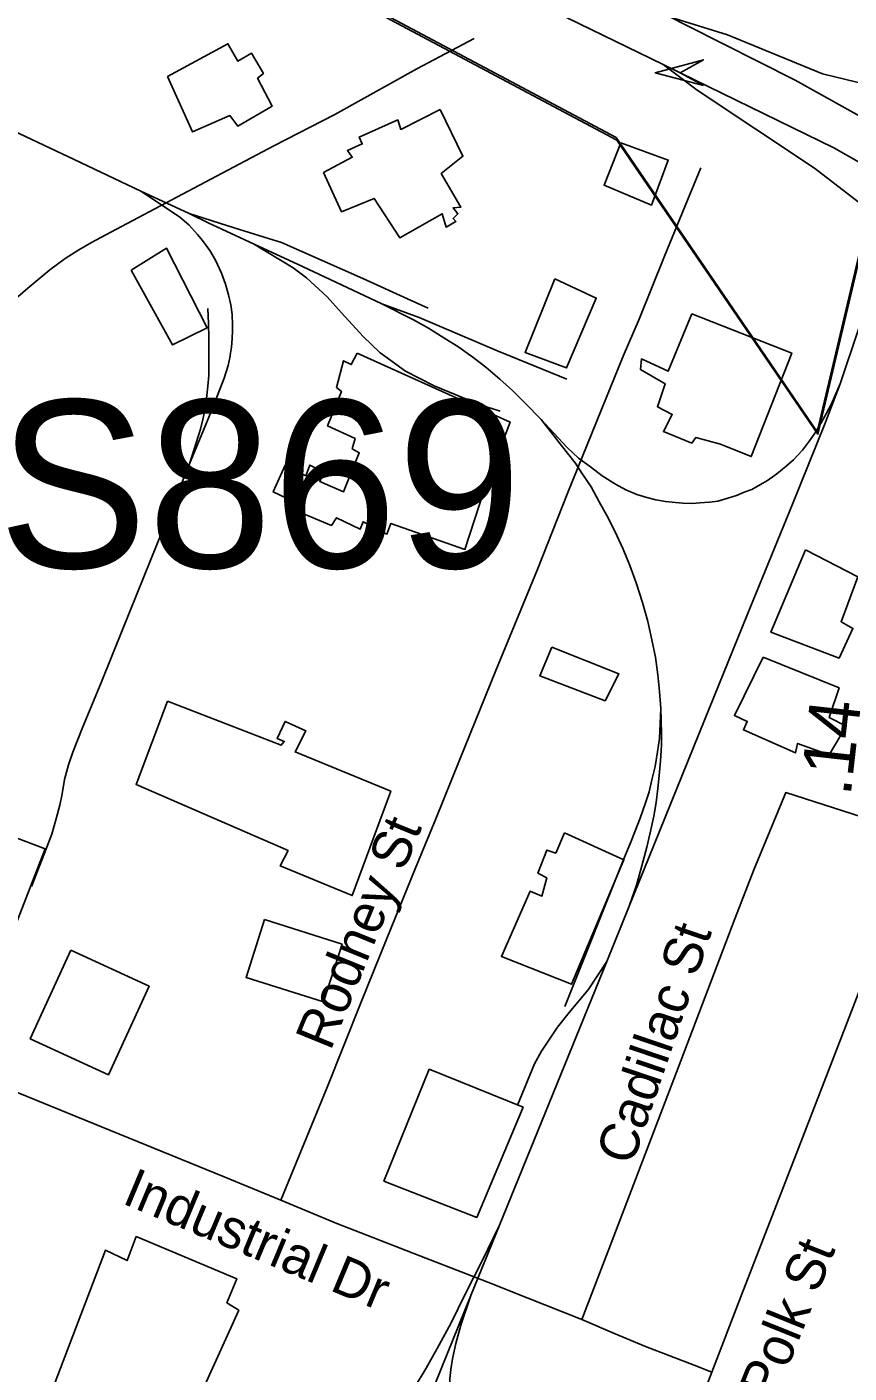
# Model space of a CAD drawing. Extents: x 1383679 to 1536984, y 460658 to 651027.
# Drawn here: x 1434816 to 1436826, y 494579 to 497871 of the extents above; entities that cross this region are included whole.
import ezdxf

# ---------------------------------------------------------------- set-up
doc = ezdxf.new("R2010")
doc.units = 0
for name, color, linetype in [('Default', 7, 'Continuous'), ('Exist Boundary Political City Limit New', 7, 'Continuous'), ('Exist Cultural Warehouse Building Footprint', 7, 'Continuous'), ('Exist Railroad Mainline', 7, 'Continuous'), ('Exist Railroad Spur', 7, 'Continuous'), ('Exist Road Non-System Type 51', 7, 'Continuous'), ('Exist Road Non-System Type 51 Label', 7, 'Continuous'), ('Exist Road Primary Interstate Divided Center Attributed', 7, 'Continuous'), ('Exist Road Primary Interstate Ramp 1 Lane Attributed', 7, 'Continuous'), ('Exist Road Primary Interstate Structure Ovrhead Sign Attributed CELL', 7, 'Continuous'), ('Exist Road Primary Interstate Structure Ovrhead Sign Number Label', 7, 'Continuous'), ('Exist Road Secondary Mileage Hundredths English Label', 7, 'Continuous'), ('Exist Road Secondary Type 51 Attributed', 7, 'Continuous'), ('Exist Road Secondary Type 51 Label', 7, 'Continuous'), ('Map Preparation Boundary City Limit Buffer Line', 7, 'Continuous')]:
    doc.layers.add(name, color=color, linetype=linetype)

msp = doc.modelspace()

# ---------------------------------------------------------------- linework, layer by layer
at = {"layer": 'Default'}
msp.add_lwpolyline([(1438555.6, 495595.6), (1438553.8, 495601.6), (1438311.5, 496009.1), (1438130.2, 496314), (1437339.2, 497105.4), (1436875.1, 497418.9), (1436748.5, 496881.1), (1436256.8, 497600.6), (1435680.2, 497907.4)], dxfattribs=at)
at = {"layer": 'Exist Boundary Political City Limit New'}
for points in [[(1438555.6, 495595.6), (1438553.8, 495601.6), (1438311.5, 496009.1), (1438130.2, 496314), (1437339.2, 497105.4), (1436875.1, 497418.9), (1436748.5, 496881.1), (1436256.8, 497600.6), (1435680.2, 497907.4)], [(1435681.9, 497901.2), (1436258.4, 497594.4), (1436750.1, 496874.9), (1436876.8, 497412.8), (1437340.9, 497099.2), (1438131.9, 496307.9), (1438313.1, 496002.9), (1438555.6, 495595.6)]]:
    msp.add_lwpolyline(points, dxfattribs=at)
at = {"layer": 'Exist Cultural Warehouse Building Footprint'}
for points in [[(1435159.9, 497750.4), (1435307.2, 497830.1), (1435331.4, 497787.9), (1435365.2, 497806.7), (1435394.2, 497757.5), (1435379.7, 497745.8), (1435415.9, 497677.8), (1435331.4, 497628.6), (1435312.1, 497654.4), (1435220.3, 497614.6), (1435159.9, 497750.4)], [(1435826.4, 497669.6), (1435729.8, 497620.4), (1435722.5, 497643.9), (1435628.4, 497601.7), (1435635.6, 497585.3), (1435599.4, 497568.9), (1435611.5, 497552.5), (1435541.4, 497515), (1435584.9, 497419), (1435664.6, 497451.8), (1435727.4, 497355.8), (1435831.2, 497414.3), (1435840.9, 497381.5), (1435865, 497395.6), (1435857.8, 497402.6), (1435869.8, 497414.3), (1435857.8, 497428.4), (1435877.1, 497430.7), (1435828.8, 497512.7), (1435881.9, 497554.9), (1435826.4, 497669.6)], [(1436268.2, 497587.7), (1436227.2, 497484.6), (1436343.1, 497435.4), (1436384.1, 497545.5), (1436268.2, 497587.7)], [(1435070.6, 497276.1), (1435157.5, 497330), (1435256.5, 497135.6), (1435172, 497093.4), (1435070.6, 497276.1)], [(1436106.5, 497255), (1436034, 497074.7), (1436135.4, 497037.2), (1436207.9, 497208.2), (1436106.5, 497255)], [(1436442.1, 497169.5), (1436384.1, 497029), (1436318.9, 497059.4), (1436316.5, 497033.7), (1436376.9, 496998.5), (1436357.6, 496942.3), (1436393.8, 496923.6), (1436372.1, 496881.4), (1436442.1, 496853.3), (1436451.8, 496867.4), (1436512.1, 496851), (1436587, 496820.5), (1436686, 497073.5), (1436442.1, 497169.5)], [(1435623.5, 497073.5), (1435609.1, 497045.4), (1435589.7, 497054.8), (1435572.8, 496989.2), (1435584.9, 496979.8), (1435551.1, 496895.5), (1435618.7, 496865), (1435611.5, 496839.3), (1435628.4, 496829.9), (1435589.7, 496733.8), (1435531.8, 496759.6), (1435541.4, 496783), (1435507.6, 496799.4), (1435498, 496773.7), (1435447.3, 496799.4), (1435418.3, 496733.8), (1435483.5, 496703.4), (1435476.3, 496687), (1435560.8, 496651.9), (1435572.8, 496670.6), (1435630.8, 496642.5), (1435638, 496661.2), (1435696, 496630.8), (1435705.6, 496656.5), (1435886.7, 496593.3), (1435935, 496740.9), (1435997.8, 496904.8), (1435623.5, 497073.5)], [(1436719.8, 496592.1), (1436635.3, 496390.7), (1436801.9, 496327.4), (1436835.7, 496400.1), (1436806.7, 496416.4), (1436847.7, 496526.5), (1436719.8, 496592.1)], [(1436099.2, 496354.4), (1436070.2, 496284.1), (1436229.6, 496223.2), (1436263.4, 496288.8), (1436099.2, 496354.4)], [(1436615.9, 496329.8), (1436545.9, 496186.9), (1436577.3, 496172.8), (1436567.7, 496151.8), (1436695.6, 496095.5), (1436700.5, 496119), (1436777.7, 496090.9), (1436818.8, 496161.1), (1436777.7, 496182.2), (1436801.9, 496254.8), (1436615.9, 496329.8)], [(1435159.9, 496222), (1435082.7, 496018.2), (1435454.5, 495856.6), (1435435.2, 495819.1), (1435611.5, 495746.5), (1435705.6, 496001.8), (1435471.4, 496097.9), (1435498, 496149.4), (1435447.3, 496172.8), (1435428, 496130.7), (1435444.9, 496123.6), (1435437.6, 496114.3), (1435159.9, 496222)], [(1434524.9, 495987.8), (1434372.8, 495608.3), (1434467, 495566.2), (1434447.6, 495521.7), (1434585.3, 495458.4), (1434611.8, 495509.9), (1434708.4, 495472.5), (1434860.5, 495861.3), (1434524.9, 495987.8)], [(1436130.6, 495899.9), (1436108.9, 495850.8), (1436087.1, 495857.8), (1436065.4, 495801.6), (1436087.1, 495789.9), (1436075.1, 495745.4), (1436046.1, 495757.1), (1435976.1, 495597.8), (1436147.5, 495529.8), (1436275.5, 495834.4), (1436130.6, 495899.9)], [(1435396.6, 495688), (1435351.8, 495546.7), (1435541.4, 495486.5), (1435586.3, 495627.8), (1435396.6, 495688)], [(1434923.3, 495613), (1435114.6, 495525.1), (1435015.1, 495308.5), (1434823.8, 495396.4), (1434923.3, 495613)], [(1435799.8, 495322.5), (1436029.2, 495228.9), (1435915.7, 494959.5), (1435688.7, 495048.5), (1435799.8, 495322.5)], [(1435082.7, 494912.6), (1435060.9, 494854.1), (1435007.8, 494879.8), (1434848.5, 494460.5), (1435176.8, 494329.4), (1435246.9, 494540.2), (1435333.8, 494732.3), (1435304.8, 494751), (1435329, 494809.6), (1435082.7, 494912.6)]]:
    msp.add_lwpolyline(points, dxfattribs=at)
at = {"layer": 'Exist Railroad Mainline'}
for p, q in [((1435094.5, 497469.7), (1435212.4, 497414.9)), ((1436233.9, 495585.5), (1436288.9, 495721.1)), ((1435971.7, 494940.5), (1436233.9, 495585.5)), ((1435901.4, 494768.3), (1435971.7, 494940.5))]:
    msp.add_line(p, q, dxfattribs=at)
for points in [[(1434041.3, 497962.9), (1434289.2, 497847.2), (1434526.5, 497735.5), (1434737, 497638.3), (1434931.7, 497546.6), (1435094.5, 497469.7)], [(1435212.4, 497414.9), (1435260.7, 497391.6), (1435292.6, 497376.4), (1435394.1, 497329.3), (1435477.7, 497291), (1435557.5, 497253.9), (1435683.7, 497194)], [(1435683.7, 497194), (1435760.8, 497155.1), (1435797.8, 497134.2), (1435835.5, 497110.9), (1435872.2, 497087.6), (1435901.2, 497067.1), (1435902.6, 497066), (1435938, 497039), (1435972.1, 497010.1), (1436003.5, 496982.2), (1436034.6, 496951.3), (1436073.3, 496911)], [(1436288.9, 495721.1), (1436362, 495901.5), (1436460.8, 496145.9), (1436577.9, 496435), (1436687.8, 496704.3), (1436765.8, 496898), (1436804.7, 496998.6), (1436849.3, 497132.2)], [(1436073.3, 496911), (1436122.3, 496848.2), (1436156.5, 496805), (1436174.4, 496777.6), (1436195.3, 496746.1), (1436215.5, 496710.1), (1436234, 496676), (1436253.8, 496637.9), (1436273.6, 496594.1), (1436290.4, 496553.7), (1436305.8, 496511.9), (1436321.1, 496463.7), (1436333.9, 496417.2), (1436344.3, 496371.9), (1436352.6, 496329.7), (1436358.7, 496286.3), (1436362.9, 496245.6), (1436366.1, 496204.1)], [(1436366.1, 496204.1), (1436367.8, 496143.3), (1436367.4, 496114.2), (1436365.5, 496076.1), (1436362, 496040.6), (1436358.7, 496008.2), (1436354.2, 495974.4), (1436348.7, 495941.1), (1436341.5, 495907.6), (1436331.9, 495865.2), (1436319.7, 495819.7), (1436306.5, 495771.8), (1436288.9, 495721.1)], [(1434992.3, 492559.8), (1435049.1, 492676), (1435089.8, 492768.5), (1435122.1, 492847.2), (1435160.8, 492941.4), (1435206.7, 493054.6), (1435211.3, 493066), (1435284.5, 493246.9), (1435342.6, 493389), (1435443.4, 493637.1), (1435553.1, 493908.6), (1435663.9, 494182.4), (1435769.7, 494443.8), (1435901.4, 494768.3)]]:
    msp.add_lwpolyline(points, dxfattribs=at)
at = {"layer": 'Exist Railroad Spur'}
for points in [[(1435213.6, 496802.9), (1435247.5, 496885.1), (1435266.2, 496930.7), (1435282.6, 496972.4), (1435297.8, 497012.1), (1435307.8, 497043), (1435312.5, 497066), (1435313, 497068.2), (1435316.1, 497088.4), (1435317.8, 497108.9), (1435318.5, 497127.6), (1435318.7, 497142.2), (1435317.6, 497168.3), (1435314.3, 497191.6), (1435308.5, 497215.6), (1435301.1, 497242), (1435291.5, 497268.7), (1435276.7, 497301), (1435262.7, 497324.1), (1435245, 497348.7), (1435232.9, 497363.8), (1435212.8, 497386.4), (1435188.8, 497406.4), (1435094.5, 497469.7)], [(1435212.4, 497414.9), (1435322.8, 497380.1), (1435396.2, 497357.2), (1435438.3, 497343.7), (1435537.7, 497299.9), (1435637.5, 497255.7), (1435755.3, 497202.5), (1435797.2, 497183.4)], [(1435369.8, 497340.6), (1435467.1, 497282.1), (1435499.7, 497257.9), (1435549.9, 497211), (1435584.7, 497172.2), (1435638.4, 497113.7), (1435679.4, 497074.5), (1435691.1, 497066), (1435741.8, 497029.2), (1435811.7, 496993.6), (1435924.5, 496947.2), (1435973.2, 496931.5)], [(1436136, 497009.5), (1435998.7, 497066), (1435968.2, 497078.5), (1435775.2, 497160.9), (1435683.7, 497194)], [(1435258.6, 497182.9), (1435260.1, 497145.7), (1435260.6, 497110.2), (1435260.8, 497076), (1435260.8, 497042.5), (1435260.4, 497018.4), (1435258.2, 496992.9), (1435255.8, 496969.8), (1435252.7, 496941.5), (1435246.2, 496911), (1435240.6, 496887.5), (1435213.6, 496802.9)], [(1436073.3, 496911), (1436136.3, 496843.2), (1436164.8, 496816.8), (1436193.7, 496795), (1436222.2, 496773.1), (1436254.7, 496752.6), (1436280.6, 496738.7), (1436306.9, 496727.4), (1436331.9, 496720.2), (1436353.9, 496714.5), (1436377, 496710.4), (1436402.2, 496707.8), (1436419.5, 496706.4), (1436443, 496706), (1436461.7, 496707.1), (1436485, 496708.9), (1436505, 496711.7), (1436529.6, 496718.4), (1436550.7, 496725.2), (1436569.4, 496733), (1436588.4, 496740), (1436609.5, 496751.9), (1436626.9, 496762.2), (1436649.5, 496777.9), (1436672.8, 496796.8), (1436690.7, 496812.5), (1436712, 496836), (1436729.6, 496859.2), (1436744.8, 496880.6), (1436758.8, 496904.7), (1436771.2, 496926.3), (1436782.5, 496948.1), (1436804.7, 496998.6)], [(1435213.6, 496802.9), (1435172.9, 496701.7), (1435118.7, 496568.5), (1435050.1, 496399.1), (1434997.8, 496269.2), (1434951.1, 496155.7), (1434927.8, 496097.6), (1434917.1, 496066.3), (1434907.8, 496030.2), (1434901.6, 495995.3), (1434896, 495968.1), (1434887.9, 495937.4), (1434876.4, 495896.9), (1434864.7, 495865), (1434826.8, 495769)], [(1436366.1, 496204.1), (1436362.9, 496130.5), (1436357.9, 496097.9), (1436352, 496062.1), (1436344.3, 496029.5), (1436337.2, 496000.3), (1436328.5, 495973.4), (1436315.2, 495936.3), (1436293, 495879.8), (1436275.6, 495836.4), (1436131, 495475.8)], [(1436233.9, 495585.5), (1436188.3, 495516.5), (1436141.5, 495460.8), (1436113.4, 495425), (1436093.8, 495395.2), (1436074.2, 495365.8), (1436056.8, 495334.9), (1436015.7, 495234.2)], [(1435971.7, 494940.5), (1435927.9, 494851.7), (1435887.5, 494772.1), (1435853.3, 494701.7), (1435819.3, 494639.1), (1435792.1, 494590.7), (1435763.8, 494543.5)], [(1435901.4, 494768.3), (1435877.2, 494695.6), (1435865, 494651.5), (1435856.8, 494614), (1435852.2, 494587.9), (1435850, 494565.3), (1435848.9, 494545.9), (1435849.1, 494526.1), (1435851.1, 494501.7), (1435857.2, 494471.7), (1435863.3, 494442.7), (1435870.7, 494422.7), (1435880.5, 494399.8), (1435889.9, 494378.3), (1435904.7, 494352.2), (1435923.8, 494323.4), (1435945.4, 494298.4), (1435961, 494280.1), (1435973.9, 494266.4), (1435993, 494249), (1436029.6, 494225.7), (1436072.9, 494205.4), (1436184.4, 494162.1)]]:
    msp.add_lwpolyline(points, dxfattribs=at)
at = {"layer": 'Exist Road Non-System Type 51'}
for points in [[(1434775.6, 497195.5), (1434818.2, 497232.5), (1434871.9, 497277.5), (1434909.6, 497304.9), (1434943.1, 497326.1), (1434973.8, 497343.6), (1435021.1, 497369.2), (1435196.5, 497462.4), (1435419.8, 497580.1), (1435569, 497657.4), (1435769.1, 497768.8), (1435909.8, 497843.2)], [(1436464.1, 497526.7), (1436425.7, 497433.5), (1436375.1, 497310.5), (1436312.8, 497156.8), (1436274.2, 497066), (1436221.2, 496935.9), (1436138.3, 496732.6), (1436063.2, 496542.8), (1435962.6, 496297.2), (1435873.4, 496077.8), (1435815.5, 495934), (1435765.4, 495812.5), (1435696, 495641.5), (1435632.4, 495484.6), (1435548.8, 495275.9), (1435436.9, 495001.6)], [(1436881.8, 495930.8), (1436671.5, 495998.8), (1436593.1, 495809.5), (1436546.6, 495690), (1436415.2, 495342.5), (1436244.3, 494896.8), (1436172.9, 494710.2)], [(1435436.9, 495001.6), (1435298.4, 495059.2), (1434936.5, 495206.7), (1434416, 495418.3)], [(1436172.9, 494710.2), (1436169.1, 494711.8), (1436039, 494762.7), (1435942.5, 494800.8), (1435776.4, 494865.2), (1435647.4, 494915.9), (1435573.9, 494944.6), (1435436.9, 495001.6)], [(1436490.6, 494580.8), (1436447.2, 494597.9), (1436328.1, 494644.1), (1436254.4, 494675.2), (1436172.9, 494710.2)]]:
    msp.add_lwpolyline(points, dxfattribs=at)
at = {"layer": 'Exist Road Primary Interstate Divided Center Attributed'}
for points in [[(1432444.6, 500897.6), (1432592.7, 500702.2), (1432919.6, 500280.5), (1433082.2, 500067.8), (1433289.1, 499810.1), (1433441.4, 499640.7), (1433705.1, 499377.6), (1433831.1, 499266.5), (1434202.9, 498965.3), (1434538.6, 498722.6), (1434822.1, 498553.9), (1435142.2, 498393.3), (1435409.3, 498259.3), (1435872.1, 498023.1), (1436372, 497779.4)], [(1436959.3, 497600.4), (1436887.3, 497633.7), (1436694.5, 497741.4), (1436429.5, 497874.5), (1436389.3, 497895.3)], [(1436372, 497779.4), (1436413.3, 497759.3), (1436788.7, 497575.4), (1436855.2, 497538), (1436941.4, 497491.7)]]:
    msp.add_lwpolyline(points, dxfattribs=at)
at = {"layer": 'Exist Road Primary Interstate Ramp 1 Lane Attributed'}
for points in [[(1436979.6, 497703.4), (1436761.4, 497756.8), (1436529.1, 497851.5), (1436389.3, 497895.3)], [(1436372, 497779.4), (1436454.7, 497716.8), (1436741.5, 497525.9), (1436859.2, 497435.1), (1436917.7, 497386.2)]]:
    msp.add_lwpolyline(points, dxfattribs=at)
at = {"layer": 'Exist Road Primary Interstate Structure Ovrhead Sign Attributed CELL'}
msp.add_lwpolyline([(1436470.1, 497727.7), (1436352.3, 497759.3), (1436470.1, 497790.8), (1436413.3, 497759.3)], close=True, dxfattribs=at)
at = {"layer": 'Exist Road Secondary Type 51 Attributed'}
msp.add_lwpolyline([(1435703.3, 492565.4), (1435727.3, 492630.1), (1435900.5, 493066), (1435901.2, 493067.9), (1435920.1, 493119.7), (1435940.1, 493171), (1436031.1, 493398.1), (1436059.4, 493468.7), (1436129.1, 493647.1), (1436185.7, 493791.7), (1436196.3, 493819.2), (1436306, 494103.4), (1436459.7, 494500.4), (1436490.6, 494580.8), (1436562.5, 494767.9), (1436702.4, 495129), (1436818.2, 495428.1), (1436994.9, 495887.1)], dxfattribs=at)
at = {"layer": 'Map Preparation Boundary City Limit Buffer Line'}
for points in [[(1438555.6, 495595.6), (1438553.8, 495601.6), (1438311.5, 496009.1), (1438130.2, 496314), (1437339.2, 497105.4), (1436875.1, 497418.9), (1436748.5, 496881.1), (1436256.8, 497600.6), (1435680.2, 497907.4)], [(1438555.6, 495595.6), (1438553.8, 495601.6), (1438311.5, 496009.1), (1438130.2, 496314), (1437339.2, 497105.4), (1436875.1, 497418.9), (1436748.5, 496881.1), (1436256.8, 497600.6), (1435680.2, 497907.4)], [(1435681.9, 497901.2), (1436258.4, 497594.4), (1436750.1, 496874.9), (1436876.8, 497412.8), (1437340.9, 497099.2), (1438131.9, 496307.9), (1438313.1, 496002.9), (1438555.6, 495595.6)]]:
    msp.add_lwpolyline(points, dxfattribs=at)

# ---------------------------------------------------------------- texts
at = {"layer": 'Exist Road Non-System Type 51 Label'}
for s, rotation, p in [('Rodney St', 67.7872, (1435558, 495364.7)), ('Cadillac St', 71.232, (1436295.7, 495083.6)), ('Industrial Dr', 337.2948, (1435045.5, 494995))]:
    msp.add_text(s, height=95, rotation=rotation, dxfattribs=at).set_placement(p)
at = {"layer": 'Exist Road Primary Interstate Structure Ovrhead Sign Number Label'}
msp.add_text('S869', height=410.1, dxfattribs=at).set_placement((1434745, 496548.3))
at = {"layer": 'Exist Road Secondary Mileage Hundredths English Label'}
msp.add_text('.14', height=125, rotation=83.6135, dxfattribs=at).set_placement((1436829.9, 495987.7))
at = {"layer": 'Exist Road Secondary Type 51 Label'}
msp.add_text('N Polk St', height=95, rotation=68.0757, dxfattribs=at).set_placement((1436595.9, 494390.7))

doc.saveas('drawing.dxf')
